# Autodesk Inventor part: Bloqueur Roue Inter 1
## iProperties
Author: Flavien MARTY
Shininess: 41.0
PropertySet Name: _Private Model Information
Created: 2001-10
Part Number: Bloqueur Roue Inter 1
Material: Par défaut
Document SubType Name: Modélisation
Designer: Flavien MARTY
Control State: 0
Master: False
Checked Out: False
PropertySet Name: Design Tracking Control
Density: 0.0
Volumn: 0.0
Area: 0.0
PropertySet Name: Model Information
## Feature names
1. Base1
